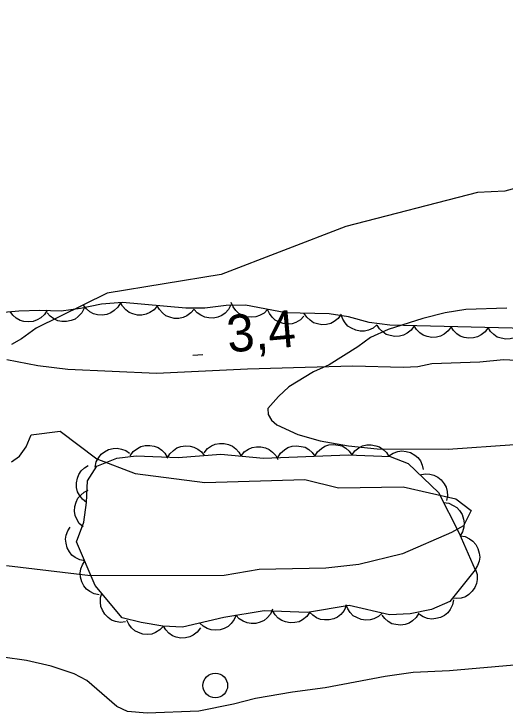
# Model space of a CAD drawing. Extents: x 336540 to 340074, y 5572036 to 5573747.
# Drawn here: x 337457 to 337496.9, y 5572600.5 to 5572657.2 of the extents above; entities that cross this region are included whole.
import ezdxf

# ---------------------------------------------------------------- set-up
doc = ezdxf.new("R2010")
doc.units = 0
for name, color, linetype in [('Niveau 2', 7, 'Continuous'), ('Niveau 22', 7, 'Continuous'), ('Niveau 3', 7, 'Continuous'), ('Niveau 36', 7, 'Continuous'), ('Niveau 44', 7, 'Continuous')]:
    doc.layers.add(name, color=color, linetype=linetype)

msp = doc.modelspace()

# ---------------------------------------------------------------- linework, layer by layer
at = {"layer": 'Niveau 2'}
for points in [[(337558.71, 5572657.2), (337552.72, 5572651.97), (337546.96, 5572648.95), (337544.77, 5572648.52), (337535.87, 5572647.72), (337526.29, 5572646.21), (337511.42, 5572645.61), (337500.7, 5572643.87), (337496.85, 5572642.83), (337494.65, 5572642.71), (337483.96, 5572639.96), (337473.86, 5572636.06), (337464.61, 5572634.56), (337458.84, 5572631.72), (337457.67, 5572630.85), (337456.84, 5572630.38)], [(337497.03, 5572633.33), (337493.71, 5572633.23), (337492.02, 5572632.94), (337490.22, 5572632.48), (337487.4, 5572631.6), (337485.96, 5572630.94), (337484.93, 5572630.18), (337482.62, 5572628.74), (337481.35, 5572628.17), (337479.33, 5572626.95), (337478.5, 5572626.16), (337477.65, 5572625.19), (337477.68, 5572624.71), (337477.94, 5572624.25), (337478.36, 5572623.85), (337480.07, 5572623.08), (337481.88, 5572622.57), (337484.19, 5572622.16), (337486.51, 5572621.91), (337492.27, 5572621.89), (337497.64, 5572622.26)], [(337456.84, 5572620.85), (337457.5, 5572621.32), (337458.05, 5572622.07), (337458.45, 5572623.06), (337460.79, 5572623.35), (337463.78, 5572621.11), (337466.89, 5572619.92), (337472.53, 5572619.19), (337480.63, 5572619.44), (337483.37, 5572618.74), (337488.62, 5572618.83), (337492.88, 5572617.86), (337494.13, 5572616.92), (337493.51, 5572615.67), (337492.53, 5572615.13), (337488.56, 5572613.39), (337485.03, 5572612.54), (337482.34, 5572612.24), (337476.93, 5572612.12), (337474.09, 5572611.65), (337463.26, 5572611.6), (337456.44, 5572612.42)], [(337497.63, 5572604.36), (337492.38, 5572603.91), (337489.42, 5572603.76), (337487.15, 5572603.43), (337482.29, 5572602.52), (337479.65, 5572602.18), (337476.65, 5572601.65), (337474.86, 5572601.19), (337472.04, 5572600.63), (337467.85, 5572600.48), (337466.25, 5572600.59), (337465.38, 5572601.01), (337462.97, 5572603.13), (337461.94, 5572603.65), (337460.07, 5572604.29), (337458.06, 5572604.74), (337456.15, 5572605.01)]]:
    msp.add_lwpolyline(points, dxfattribs=at)
at = {"layer": 'Niveau 22'}
msp.add_lwpolyline([(337456.48, 5572629.16), (337458.99, 5572628.68), (337461.42, 5572628.38), (337468.61, 5572628.06), (337475.99, 5572628.41), (337480.68, 5572628.55), (337484.54, 5572628.64), (337488.62, 5572628.54), (337489.81, 5572628.61), (337490.94, 5572628.84), (337494.84, 5572628.97), (337496.76, 5572629.17), (337502.99, 5572628.85)], dxfattribs=at)
at = {"layer": 'Niveau 3'}
msp.add_line((337471.56, 5572629.51), (337472.37, 5572629.58), dxfattribs=at)
at = {"layer": 'Niveau 36'}
msp.add_circle((337473.379, 5572602.711), 1, dxfattribs=at)
at = {"layer": 'Niveau 44'}
for points in [[(337499.65, 5572631.65), (337487.54, 5572631.94), (337485.87, 5572632.16), (337484.18, 5572632.63), (337482.61, 5572632.86), (337479.1, 5572632.95), (337475.84, 5572633.56), (337474.27, 5572633.55), (337472.54, 5572633.34), (337470.99, 5572633.32), (337465.84, 5572633.78), (337464.15, 5572633.66), (337462.44, 5572633.29), (337460.88, 5572633.09), (337459.14, 5572633.15), (337457.45, 5572633.08), (337454.09, 5572632.79)], [(337465.69, 5572633.77), (337465.48, 5572633.41), (337465.18, 5572633.13), (337464.91, 5572632.94), (337464.58, 5572632.82), (337464.21, 5572632.77), (337463.83, 5572632.8), (337463.51, 5572632.87), (337463.21, 5572633.04), (337462.92, 5572633.27), (337462.69, 5572633.56)], [(337468.67, 5572633.53), (337468.41, 5572633.2), (337468.07, 5572632.98), (337467.78, 5572632.83), (337467.43, 5572632.77), (337467.06, 5572632.77), (337466.69, 5572632.87), (337466.39, 5572632.98), (337466.11, 5572633.2), (337465.86, 5572633.48), (337465.69, 5572633.79)], [(337471.66, 5572633.26), (337471.4, 5572632.94), (337471.06, 5572632.71), (337470.77, 5572632.56), (337470.42, 5572632.5), (337470.05, 5572632.5), (337469.68, 5572632.6), (337469.37, 5572632.72), (337469.1, 5572632.94), (337468.85, 5572633.21), (337468.67, 5572633.53)], [(337474.65, 5572633.6), (337474.46, 5572633.22), (337474.18, 5572632.93), (337473.92, 5572632.73), (337473.59, 5572632.6), (337473.23, 5572632.52), (337472.85, 5572632.54), (337472.52, 5572632.59), (337472.21, 5572632.75), (337471.91, 5572632.96), (337471.67, 5572633.23)], [(337477.62, 5572633.23), (337477.33, 5572632.93), (337476.97, 5572632.74), (337476.66, 5572632.62), (337476.31, 5572632.59), (337475.94, 5572632.63), (337475.58, 5572632.76), (337475.29, 5572632.91), (337475.04, 5572633.15), (337474.82, 5572633.45), (337474.67, 5572633.78)], [(337459.74, 5572633.17), (337459.52, 5572632.82), (337459.22, 5572632.55), (337458.94, 5572632.37), (337458.61, 5572632.26), (337458.24, 5572632.22), (337457.86, 5572632.26), (337457.54, 5572632.34), (337457.24, 5572632.52), (337456.96, 5572632.76), (337456.75, 5572633.05)], [(337462.73, 5572633.33), (337462.54, 5572632.95), (337462.26, 5572632.66), (337462, 5572632.45), (337461.68, 5572632.32), (337461.31, 5572632.24), (337460.93, 5572632.26), (337460.61, 5572632.31), (337460.29, 5572632.46), (337459.99, 5572632.68), (337459.75, 5572632.95)], [(337480.57, 5572632.67), (337480.28, 5572632.38), (337479.92, 5572632.18), (337479.61, 5572632.07), (337479.26, 5572632.04), (337478.89, 5572632.08), (337478.53, 5572632.21), (337478.24, 5572632.35), (337477.99, 5572632.6), (337477.77, 5572632.9), (337477.62, 5572633.23)], [(337483.59, 5572632.83), (337483.35, 5572632.49), (337483.03, 5572632.25), (337482.74, 5572632.08), (337482.4, 5572632), (337482.03, 5572631.98), (337481.66, 5572632.05), (337481.34, 5572632.15), (337481.06, 5572632.35), (337480.79, 5572632.61), (337480.6, 5572632.91)], [(337486.49, 5572631.99), (337486.17, 5572631.72), (337485.8, 5572631.55), (337485.48, 5572631.46), (337485.13, 5572631.47), (337484.77, 5572631.54), (337484.42, 5572631.7), (337484.14, 5572631.87), (337483.91, 5572632.13), (337483.72, 5572632.45), (337483.6, 5572632.79)], [(337489.5, 5572631.89), (337489.26, 5572631.55), (337488.94, 5572631.3), (337488.65, 5572631.14), (337488.31, 5572631.06), (337487.94, 5572631.03), (337487.56, 5572631.11), (337487.25, 5572631.2), (337486.96, 5572631.4), (337486.69, 5572631.66), (337486.5, 5572631.96)], [(337492.5, 5572631.82), (337492.26, 5572631.48), (337491.93, 5572631.23), (337491.65, 5572631.07), (337491.31, 5572630.99), (337490.94, 5572630.96), (337490.56, 5572631.04), (337490.25, 5572631.13), (337489.96, 5572631.33), (337489.69, 5572631.59), (337489.5, 5572631.89)], [(337495.5, 5572631.75), (337495.26, 5572631.41), (337494.93, 5572631.16), (337494.65, 5572631), (337494.31, 5572630.91), (337493.94, 5572630.89), (337493.56, 5572630.96), (337493.25, 5572631.06), (337492.96, 5572631.26), (337492.69, 5572631.52), (337492.5, 5572631.82)], [(337498.5, 5572631.68), (337498.25, 5572631.34), (337497.93, 5572631.09), (337497.65, 5572630.92), (337497.3, 5572630.84), (337496.94, 5572630.82), (337496.56, 5572630.89), (337496.25, 5572630.99), (337495.96, 5572631.19), (337495.69, 5572631.45), (337495.5, 5572631.75)], [(337466.48, 5572621.36), (337466.73, 5572621.69), (337467.06, 5572621.94), (337467.34, 5572622.1), (337467.69, 5572622.18), (337468.06, 5572622.2), (337468.43, 5572622.12), (337468.74, 5572622.02), (337469.03, 5572621.82), (337469.29, 5572621.56), (337469.48, 5572621.25)], [(337469.48, 5572621.15), (337469.69, 5572621.52), (337469.99, 5572621.79), (337470.26, 5572621.99), (337470.59, 5572622.1), (337470.95, 5572622.16), (337471.34, 5572622.13), (337471.65, 5572622.06), (337471.96, 5572621.89), (337472.25, 5572621.66), (337472.48, 5572621.38)], [(337472.48, 5572621.6), (337472.74, 5572621.93), (337473.08, 5572622.15), (337473.38, 5572622.3), (337473.72, 5572622.36), (337474.09, 5572622.36), (337474.46, 5572622.26), (337474.77, 5572622.14), (337475.04, 5572621.92), (337475.29, 5572621.65), (337475.47, 5572621.33)], [(337475.47, 5572621.33), (337475.73, 5572621.66), (337476.07, 5572621.88), (337476.36, 5572622.03), (337476.71, 5572622.09), (337477.08, 5572622.09), (337477.45, 5572621.99), (337477.76, 5572621.87), (337478.03, 5572621.65), (337478.28, 5572621.38), (337478.45, 5572621.06)], [(337478.46, 5572621.21), (337478.68, 5572621.57), (337478.99, 5572621.83), (337479.26, 5572622.02), (337479.6, 5572622.12), (337479.96, 5572622.16), (337480.34, 5572622.11), (337480.66, 5572622.04), (337480.96, 5572621.85), (337481.24, 5572621.61), (337481.46, 5572621.32)], [(337481.46, 5572621.32), (337481.68, 5572621.68), (337481.98, 5572621.94), (337482.26, 5572622.13), (337482.6, 5572622.23), (337482.96, 5572622.27), (337483.34, 5572622.22), (337483.66, 5572622.15), (337483.96, 5572621.96), (337484.24, 5572621.72), (337484.45, 5572621.43)], [(337484.45, 5572621.41), (337484.7, 5572621.75), (337485.02, 5572621.99), (337485.31, 5572622.15), (337485.66, 5572622.23), (337486.02, 5572622.25), (337486.4, 5572622.17), (337486.71, 5572622.07), (337487, 5572621.87), (337487.26, 5572621.61), (337487.45, 5572621.3)], [(337462.93, 5572617.57), (337463.02, 5572619.32), (337463.78, 5572620.5), (337465.4, 5572621.16), (337466.97, 5572621.34), (337470.38, 5572621.22), (337473.83, 5572621.48), (337477.28, 5572621.17), (337484.16, 5572621.42), (337487.55, 5572621.3), (337489.03, 5572620.72), (337491.48, 5572618.37), (337493.12, 5572615.13), (337494.47, 5572612.11), (337492.39, 5572609.52), (337490.92, 5572608.89), (337489.19, 5572608.54), (337487.5, 5572608.46), (337484.25, 5572609.21), (337480.86, 5572608.64), (337477.35, 5572608.78), (337474.07, 5572608.22), (337470.71, 5572607.45), (337469.11, 5572607.53), (337467.37, 5572607.82), (337465.83, 5572608.19), (337463.64, 5572610.84), (337462.13, 5572614.36), (337462.71, 5572615.97), (337462.93, 5572617.57)], [(337463.64, 5572620.44), (337463.72, 5572620.85), (337463.92, 5572621.21), (337464.11, 5572621.47), (337464.4, 5572621.68), (337464.72, 5572621.85), (337465.1, 5572621.94), (337465.42, 5572621.97), (337465.77, 5572621.9), (337466.11, 5572621.77), (337466.41, 5572621.57)], [(337487.46, 5572621.34), (337487.8, 5572621.57), (337488.19, 5572621.7), (337488.52, 5572621.75), (337488.87, 5572621.71), (337489.22, 5572621.61), (337489.55, 5572621.41), (337489.81, 5572621.21), (337490.01, 5572620.93), (337490.17, 5572620.59), (337490.25, 5572620.24)], [(337462.93, 5572617.57), (337462.6, 5572617.82), (337462.36, 5572618.15), (337462.2, 5572618.44), (337462.13, 5572618.78), (337462.11, 5572619.15), (337462.2, 5572619.53), (337462.3, 5572619.84), (337462.51, 5572620.12), (337462.78, 5572620.38), (337463.08, 5572620.57)], [(337489.98, 5572619.81), (337490.39, 5572619.9), (337490.79, 5572619.87), (337491.11, 5572619.79), (337491.42, 5572619.62), (337491.71, 5572619.39), (337491.94, 5572619.08), (337492.1, 5572618.8), (337492.18, 5572618.46), (337492.2, 5572618.09), (337492.14, 5572617.73)], [(337462.66, 5572615.58), (337462.35, 5572615.86), (337462.14, 5572616.21), (337462, 5572616.51), (337461.96, 5572616.86), (337461.98, 5572617.23), (337462.09, 5572617.6), (337462.22, 5572617.9), (337462.46, 5572618.16), (337462.74, 5572618.4), (337463.07, 5572618.56)], [(337491.89, 5572617.55), (337492.31, 5572617.5), (337492.68, 5572617.33), (337492.96, 5572617.16), (337493.19, 5572616.9), (337493.39, 5572616.58), (337493.5, 5572616.22), (337493.57, 5572615.9), (337493.53, 5572615.55), (337493.42, 5572615.19), (337493.25, 5572614.87)], [(337462.79, 5572612.82), (337462.38, 5572612.9), (337462.02, 5572613.09), (337461.75, 5572613.28), (337461.54, 5572613.55), (337461.36, 5572613.88), (337461.27, 5572614.25), (337461.23, 5572614.58), (337461.29, 5572614.92), (337461.41, 5572615.27), (337461.61, 5572615.57)], [(337493.24, 5572614.87), (337493.65, 5572614.8), (337494.01, 5572614.61), (337494.28, 5572614.42), (337494.5, 5572614.15), (337494.68, 5572613.83), (337494.78, 5572613.46), (337494.83, 5572613.13), (337494.77, 5572612.79), (337494.65, 5572612.44), (337494.46, 5572612.13)], [(337463.97, 5572610.06), (337463.56, 5572610.14), (337463.2, 5572610.33), (337462.93, 5572610.52), (337462.72, 5572610.8), (337462.54, 5572611.12), (337462.45, 5572611.5), (337462.41, 5572611.82), (337462.47, 5572612.17), (337462.6, 5572612.51), (337462.79, 5572612.82)], [(337494.48, 5572612.13), (337494.61, 5572611.73), (337494.61, 5572611.32), (337494.57, 5572610.99), (337494.42, 5572610.67), (337494.22, 5572610.37), (337493.93, 5572610.11), (337493.67, 5572609.92), (337493.33, 5572609.81), (337492.96, 5572609.76), (337492.61, 5572609.79)], [(337466.09, 5572607.87), (337465.68, 5572607.83), (337465.28, 5572607.91), (337464.96, 5572608.02), (337464.68, 5572608.23), (337464.42, 5572608.49), (337464.23, 5572608.82), (337464.1, 5572609.12), (337464.06, 5572609.47), (337464.08, 5572609.84), (337464.18, 5572610.19)], [(337492.71, 5572609.66), (337492.63, 5572609.25), (337492.44, 5572608.89), (337492.25, 5572608.62), (337491.97, 5572608.4), (337491.64, 5572608.23), (337491.27, 5572608.14), (337490.95, 5572608.09), (337490.6, 5572608.15), (337490.25, 5572608.28), (337489.95, 5572608.47)], [(337483.99, 5572609.17), (337483.82, 5572608.79), (337483.55, 5572608.48), (337483.3, 5572608.26), (337482.98, 5572608.12), (337482.62, 5572608.03), (337482.24, 5572608.03), (337481.91, 5572608.06), (337481.59, 5572608.2), (337481.28, 5572608.41), (337481.03, 5572608.67)], [(337486.92, 5572608.59), (337486.61, 5572608.31), (337486.24, 5572608.13), (337485.93, 5572608.03), (337485.58, 5572608.02), (337485.21, 5572608.07), (337484.86, 5572608.22), (337484.57, 5572608.37), (337484.33, 5572608.63), (337484.12, 5572608.93), (337483.99, 5572609.27)], [(337475.06, 5572608.45), (337474.91, 5572608.06), (337474.66, 5572607.74), (337474.42, 5572607.51), (337474.11, 5572607.34), (337473.76, 5572607.23), (337473.37, 5572607.21), (337473.05, 5572607.22), (337472.72, 5572607.35), (337472.4, 5572607.53), (337472.13, 5572607.78)], [(337478.03, 5572608.9), (337477.85, 5572608.51), (337477.59, 5572608.21), (337477.34, 5572607.99), (337477.02, 5572607.85), (337476.66, 5572607.75), (337476.28, 5572607.75), (337475.95, 5572607.79), (337475.63, 5572607.93), (337475.32, 5572608.13), (337475.07, 5572608.39)], [(337481.03, 5572608.63), (337480.79, 5572608.3), (337480.46, 5572608.05), (337480.17, 5572607.89), (337479.83, 5572607.82), (337479.46, 5572607.8), (337479.08, 5572607.88), (337478.77, 5572607.98), (337478.49, 5572608.18), (337478.23, 5572608.45), (337478.04, 5572608.75)], [(337489.9, 5572608.57), (337489.68, 5572608.22), (337489.38, 5572607.95), (337489.1, 5572607.76), (337488.77, 5572607.66), (337488.4, 5572607.61), (337488.02, 5572607.65), (337487.7, 5572607.72), (337487.4, 5572607.9), (337487.12, 5572608.14), (337486.9, 5572608.43)], [(337469.17, 5572607.52), (337468.88, 5572607.22), (337468.53, 5572607.02), (337468.22, 5572606.89), (337467.87, 5572606.86), (337467.51, 5572606.89), (337467.14, 5572607.01), (337466.85, 5572607.15), (337466.59, 5572607.39), (337466.36, 5572607.69), (337466.21, 5572608.01)], [(337472.17, 5572607.38), (337471.92, 5572607.04), (337471.59, 5572606.8), (337471.3, 5572606.65), (337470.95, 5572606.57), (337470.59, 5572606.56), (337470.21, 5572606.64), (337469.9, 5572606.75), (337469.62, 5572606.95), (337469.36, 5572607.22), (337469.17, 5572607.53)]]:
    msp.add_lwpolyline(points, dxfattribs=at)

# ---------------------------------------------------------------- texts
at = {"layer": 'Niveau 3'}
msp.add_text('3,4    ', height=2.9999, rotation=5.0475, dxfattribs=at).set_placement((337474.44, 5572629.73))

doc.saveas('drawing.dxf')
